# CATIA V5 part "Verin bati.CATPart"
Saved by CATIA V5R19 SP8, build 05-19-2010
Part number: Vérin bati
Bounding box of the stored display mesh (mm): x -45 to 45, y -89.818 to 150, z -45 to 45
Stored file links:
  J:\Travail\2e année\IAO\Projet\Verin bati.CATPart
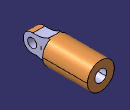
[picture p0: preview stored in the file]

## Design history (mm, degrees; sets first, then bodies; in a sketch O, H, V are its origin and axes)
Body1 (main body)
  Sketch1 on zx-plane, origin (0, 0, 0), H (-1, 0, 0), V (0, 0, 1)
    circle A1 centre (0, 0) radius 45
    radius A1 = 45
  Pad1: profile Sketch1, direction (0, 1, 0), length 150
  SolidCombine1: FirstComponentProfile Sketch5, FirstComponentDirection Sketch5, SecondComponentProfile Sketch4, SecondComponentDirection Sketch4
  Sketch2 on face of SolidCombine1 from Sketch4.L1, origin (20, -42.0705, -0.8635), H (0, 1, 0), V (0, 0, 1)
    point P1 (-17.9295, 0.8635)
    reference projected arc E1 centre (-17.9295, 0.8635) radius 30 from (-15.5126, 30.766) to (-15.5126, -29.039) ccw from edge [face of SolidCombine1 from Sketch4.L1 | face of SolidCombine1 from Sketch5.A1]
    concentricity: P1 E1
  Hole1: placed by Sketch2, at (20, -60, 0) direction (-1, 0, 0), diameter 30, through (limit type 6)
  Sketch3 on end face of Pad1, origin (0, 150, 0), H (1, 0, 0), V (0, 0, -1)
    point P1 (0, 0)
  Hole2: placed by Sketch3, at (0, 150, 0) direction (0, -1, 0), diameter 40, depth 180
  Sketch4 on start face of Pad1, origin (0, 0, 0), H (1, 0, 0), V (0, 0, 1)
    arc A1 centre (0, 0) radius 45 from (20, 40.3113) to (-20, 40.3113) ccw
    point P1 (0, 45)
    line L1 (20, 40.3113) -> (20, -40.3113)
    line L2 (-20, 40.3113) -> (-20, -40.3113)
    point P5 (-20, -40.3113)
    arc A2 centre (0, 0) radius 45 from (-20, -40.3113) to (20, -40.3113) ccw
    reference projected circle E1 centre (0, 0) radius 45 from edge [start face of Pad1 | face of Pad1 from Sketch1.A1]
    distance L1 V = 20
    distance L2 V = 20
    coincidence: A1 P1, P1 V, P5 A1, A1 A2, A1 E1
    vertical: L1 V, L2 V
  Sketch5 on yz-plane, origin (0, 0, 0), H (0, 1, 0), V (0, 0, 1)
    arc A1 centre (-60, 0) radius 30 from (-57.5831, 29.9025) to (-57.5831, -29.9025) ccw
    point P1 (-60, 0)
    line L1 (0, 45) -> (0, 45)
    point P2 (-37.4223, 19.7546)
    point P3 (0, 45)
    axis line L2 (23.5557, 0) -> (-180.0879, 0)
    point P4 (23.5557, 0)
    point P6 (0, -45)
    point P7 (-37.4223, 19.7546)
    line L3 (0, 45) -> (0, -45)
    arc A2 centre (-50.3325, 119.6099) radius 90 from (-57.5831, 29.9025) to (0, 45) ccw
    point P8 (-57.5831, 29.9025)
    point P9 (0, 45)
    point P11 (0, -45)
    point P12 (-57.5831, -29.9025)
    arc A3 centre (-50.3325, -119.6099) radius 90 from (-57.5831, -29.9025) to (0, -45) cw
    distance P3 O = 45
    radius A1 = 30
    distance O P1 = 60
    radius A2 = 90
    coincidence: P1 H, P2 A1, P3 V, P4 H, L1 P7, A1 P7, L1 P2, P11 P6
    horizontal: L2 H
    symmetry: P3 P6 L2, P9 P11 L2, P8 P12 L2, A2 A3 L2
    vertical: L3 V
    tangency: A2 A1, A2 L1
